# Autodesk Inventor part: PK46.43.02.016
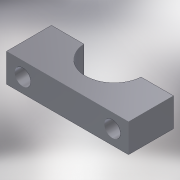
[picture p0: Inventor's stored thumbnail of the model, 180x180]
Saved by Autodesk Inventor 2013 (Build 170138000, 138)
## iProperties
Shininess: 64.0
Length Units: 11269
Angle Units: 11279
Time Units: 11290
Mass Units: 11283
Length Display Precision: 3
Angle Display Precision: 2
Compacted: True
Part Number: PK46.43.02.016
Document SubType Name: Modeling
Created: 2004-12
Material: Сталь высокопрочная низколегированная
Designer: ELarisa
Manufacturer: Standard
Standards Organization: Custom
Density: 7.84 g/cm^3
Density: 0.0
Volumn: 0.0
Area: 0.0
PropertySet Name: Model Information
Control State: 0
Master: False
Checked Out: False
Checked Out Date: 2008-10-09
Last Check In Date: 2008-10-09
Author: ELarisa
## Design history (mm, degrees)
sketch "Эскиз1"
  geometry: L1 (-23.935, -9.108)-(-23.935, 15.892); L2 (44.065, 15.892)-(44.065, -9.108); L3 (44.065, -9.108)-(-23.935, -9.108); L4 (-23.935, 15.892)-(-5.904, 15.892); L5 (26.034, 15.892)-(44.065, 15.892); A1 r 16 centre (10.065, 16.892) between (-5.904, 15.892) and (26.034, 15.892)
  constraints: 10 end point, 3 parallel, 2 perpendicular, 2 point on circle, 1 centre point, 1 vertical
  dimensions: "d0" = 68 distance of L2.end L1.start; "d2" = 25 distance of L1.start L1.end; "d3" = 34 distance from line of L1 A1.centre; "d4" = 32 diameter of A1; "d5" = 1 distance from line of A1.centre L4; "d6" = 25 distance of L2.start L2.end
extrude "Выдавливание1" new body sketch "Эскиз1" distance "d7" = 16; taper "d8" = 0 deg
sketch "Эскиз2"
  geometry: L1 (0, -16)-(18.031, -16) reference; L2 (0, 0)-(0, -16) reference; L3 (49.969, -16)-(68, -16) reference; L4 (68, 0)-(68, -16) reference; L5 (49.969, 0)-(68, 0) reference; L6 (49.969, 0)-(49.969, -16) reference; 2 further points
  dimensions: "d9" = 50 distance of point (59, -8) point (9, -8); "d10" = 8 distance from line of L1 point (9, -8); "d11" = 8 distance from line of point (59, -8) L3; "d12" = 9 distance from line of point (9, -8) L2
hole "Отверстие1" sketch "Эскиз2" diameter "d13" = 9; stored, may be unused: countersink angle "d17" = 82 deg, drill point angle "d19" = 118 deg; dims "d14" = 6, "d15" = 4, "d16" = 2, "d18" = 8
body "Solid1"
node "Спроецированная петля1"
other parameters: "d1" = 1
